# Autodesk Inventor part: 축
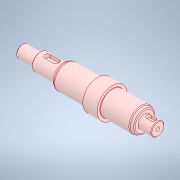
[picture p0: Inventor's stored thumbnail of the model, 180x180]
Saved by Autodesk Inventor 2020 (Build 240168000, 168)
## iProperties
Created: 2024-04
Part Number: 축
Material: 강철, 연강
Document SubType Name: Modeling
Designer: oem
Density: 7.86 g/cm^3
Appearance: 기본값
Author: jhkim
Sending System: Autodesk Inventor 2025
Preprocessor: ST-DEVELOPER v20
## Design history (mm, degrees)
feature "솔리드1"
node "솔리드2"
